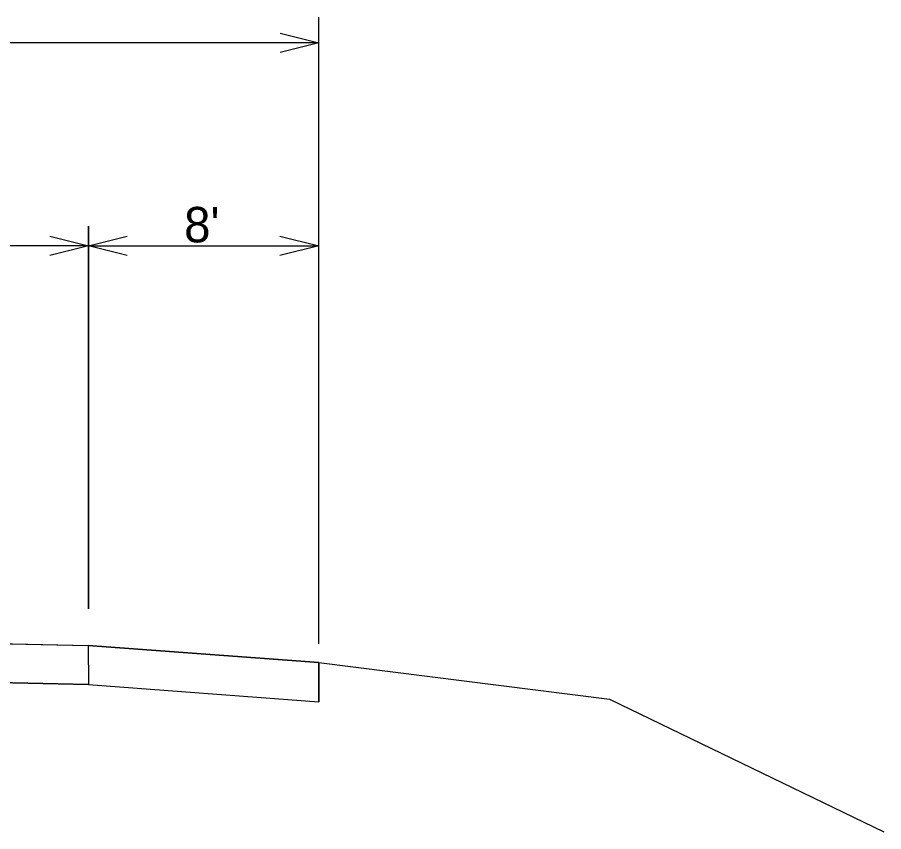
# Model space of a CAD drawing. Extents: x 10133 to 81668, y 4856 to 11018.
# Drawn here: x 12580.1 to 12946.8, y 7439.2 to 7783.8 of the extents above; entities that cross this region are included whole.
import ezdxf

# ---------------------------------------------------------------- set-up
doc = ezdxf.new("R2010")
doc.units = 0
for name, color, linetype in [('dsnXsPCCPavementBottom', 7, 'Continuous'), ('dsnXsShldrEarthFill', 7, 'Continuous'), ('dsnXsShldrGranular', 7, 'Continuous'), ('dsnXsShldrGranularBottom', 7, 'Continuous'), ('dsnXsShldrSpecialBackBottom', 7, 'Continuous')]:
    doc.layers.add(name, color=color, linetype=linetype)

msp = doc.modelspace()

# ---------------------------------------------------------------- linework, layer by layer
at = {"layer": 'dsnXsPCCPavementBottom'}
for p, q in [((12707.67, 7518.67), (12707.67, 7783.78)), ((12707.71, 7773.03), (12115.5, 7773.03)), ((12610.26, 7533.54), (12610.26, 7695.4)), ((12610.26, 7695.4), (12610.26, 7533.54)), ((12610.26, 7695.4), (12610.26, 7533.54)), ((12610.26, 7687.08), (12411.58, 7687.08)), ((12610.26, 7687.08), (12707.67, 7687.08))]:
    msp.add_line(p, q, dxfattribs=at)
for points in [[(12691.32, 7777.13), (12707.71, 7773.03), (12691.32, 7768.94)], [(12593.87, 7691.18), (12610.26, 7687.08), (12593.87, 7682.99)], [(12626.65, 7682.99), (12610.26, 7687.08), (12626.65, 7691.18)], [(12691.27, 7691.18), (12707.67, 7687.08), (12691.27, 7682.99)]]:
    msp.add_lwpolyline(points, dxfattribs=at)
at = {"layer": 'dsnXsShldrGranular'}
msp.add_line((12610.26, 7501.48), (12411.23, 7505.71), dxfattribs=at)
msp.add_lwpolyline([(12411.58, 7522.26), (12610.02, 7518.04), (12610.26, 7501.48)], dxfattribs=at)
msp.add_lwpolyline([(12707.67, 7510.78), (12610.02, 7518.04), (12610.26, 7501.48), (12707.67, 7494.18)], close=True, dxfattribs=at)
at = {"layer": 'dsnXsShldrGranularBottom'}
for p, q in [((12411.58, 7522.26), (12610.02, 7518.04)), ((12610.02, 7518.04), (12610.26, 7501.48)), ((12610.02, 7518.04), (12610.26, 7501.48)), ((12610.02, 7518.04), (12610.26, 7501.48)), ((12610.02, 7518.04), (12610.26, 7501.48)), ((12707.67, 7510.78), (12830.77, 7495.31)), ((12411.23, 7505.71), (12610.26, 7501.48)), ((12830.77, 7495.31), (12946.76, 7439.19))]:
    msp.add_line(p, q, dxfattribs=at)
at = {"layer": 'dsnXsShldrSpecialBackBottom'}
for p, q in [((12610.02, 7518.04), (12707.67, 7510.78)), ((12707.67, 7510.78), (12707.67, 7494.18)), ((12610.26, 7501.48), (12707.67, 7494.18))]:
    msp.add_line(p, q, dxfattribs=at)

# ---------------------------------------------------------------- texts
at = {"layer": 'dsnXsShldrEarthFill'}
msp.add_text("8'", height=15, rotation=0, dxfattribs=at).set_placement((12650.69, 7688.55))

doc.saveas('drawing.dxf')
